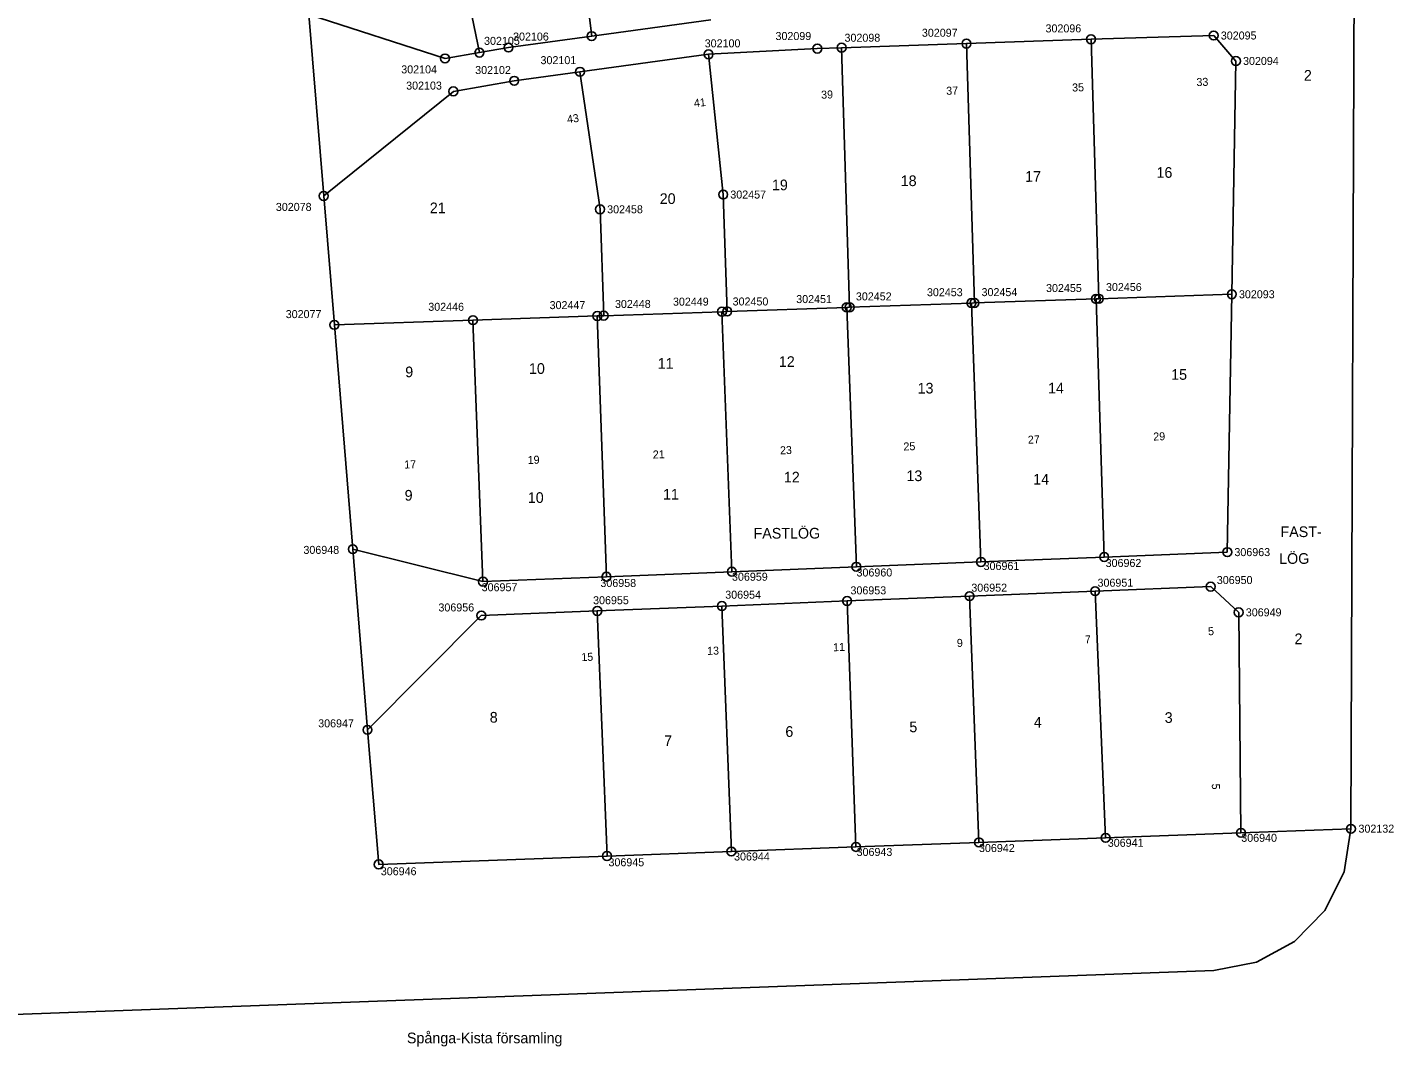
# Model space of a CAD drawing. Extents: x 141995 to 152570, y 6580184 to 6586000.
# Drawn here: x 142727.8 to 142881.4, y 6585375.4 to 6585490 of the extents above; entities that cross this region are included whole.
import ezdxf

# ---------------------------------------------------------------- set-up
doc = ezdxf.new("R2010")
doc.units = 0
for name, color, linetype in [('Level 10', 7, 'Continuous'), ('Level 13', 7, 'Continuous'), ('Level 5', 7, 'Continuous'), ('Level 51', 7, 'Continuous'), ('Level 53', 7, 'Continuous'), ('Level 54', 7, 'Continuous'), ('Level 55', 7, 'Continuous'), ('Level 57', 7, 'Continuous'), ('Level 58', 7, 'Continuous'), ('Level 59', 7, 'Continuous'), ('Level 6', 7, 'Continuous'), ('Level 7', 7, 'Continuous')]:
    doc.layers.add(name, color=color, linetype=linetype)

msp = doc.modelspace()

# ---------------------------------------------------------------- linework, layer by layer
at = {"layer": 'Level 10'}
for centre in [(142791.21, 6585489), (142833.35, 6585488.16), (142847.36, 6585488.65), (142861.15, 6585489.07), (142774.72, 6585486.49), (142778.59, 6585487.15), (142781.86, 6585487.72), (142804.35, 6585486.96), (142816.58, 6585487.6), (142819.31, 6585487.7), (142789.89, 6585484.99), (142863.65, 6585486.2), (142782.5, 6585483.98), (142775.66, 6585482.79), (142806, 6585471.19), (142761.08, 6585471.03), (142792.15, 6585469.53), (142833.91, 6585458.99), (142834.25, 6585459), (142847.92, 6585459.46), (142848.24, 6585459.47), (142863.19, 6585459.98), (142791.84, 6585457.54), (142792.56, 6585457.57), (142805.86, 6585458.02), (142806.45, 6585458.05), (142819.89, 6585458.51), (142820.21, 6585458.52), (142762.28, 6585456.54), (142777.86, 6585457.07), (142764.35, 6585431.32), (142834.98, 6585429.89), (142848.84, 6585430.44), (142862.68, 6585430.99), (142792.87, 6585428.22), (142806.97, 6585428.79), (142820.97, 6585429.34), (142778.99, 6585427.67), (142847.82, 6585426.6), (142860.81, 6585427.11), (142819.93, 6585425.5), (142833.7, 6585426.04), (142778.8, 6585423.86), (142791.84, 6585424.38), (142805.85, 6585424.93), (142863.96, 6585424.22), (142766, 6585411.01), (142864.22, 6585399.43), (142876.58, 6585399.88), (142820.93, 6585397.85), (142834.76, 6585398.35), (142849, 6585398.87), (142767.26, 6585395.88), (142792.94, 6585396.82), (142806.92, 6585397.33)]:
    msp.add_circle(centre, 0.5, dxfattribs=at)
at = {"layer": 'Level 13'}
for points in [[(142876.58, 6585399.88), (142875.82, 6585395.06)], [(142875.82, 6585395.06), (142873.64, 6585390.7)], [(142873.64, 6585390.7), (142870.24, 6585387.2)], [(142865.96, 6585384.89), (142870.24, 6585387.2)], [(142865.96, 6585384.89), (142861.17, 6585383.96)], [(142861.17, 6585383.96), (142627.09, 6585375.39)]]:
    msp.add_lwpolyline(points, dxfattribs=at)
at = {"layer": 'Level 5'}
for points in [[(142877, 6585504.71), (142876.58, 6585399.88)], [(142761.08, 6585471.03), (142759.4, 6585491.42)], [(142762.28, 6585456.54), (142761.08, 6585471.03)], [(142762.28, 6585456.54), (142764.35, 6585431.32)], [(142766, 6585411.01), (142764.35, 6585431.32)], [(142767.26, 6585395.88), (142766, 6585411.01)], [(142864.22, 6585399.43), (142849, 6585398.87)], [(142864.22, 6585399.43), (142876.58, 6585399.88)], [(142834.76, 6585398.35), (142820.93, 6585397.85)], [(142849, 6585398.87), (142834.76, 6585398.35)], [(142792.94, 6585396.82), (142767.26, 6585395.88)], [(142806.92, 6585397.33), (142792.94, 6585396.82)], [(142820.93, 6585397.85), (142806.92, 6585397.33)]]:
    msp.add_lwpolyline(points, dxfattribs=at)
at = {"layer": 'Level 6'}
msp.add_lwpolyline([(142705.65, 6585551.64), (142759.4, 6585491.42), (142761.08, 6585471.03), (142762.28, 6585456.54), (142764.35, 6585431.32), (142766, 6585411.01), (142767.26, 6585395.88), (142792.94, 6585396.82), (142806.92, 6585397.33), (142820.93, 6585397.85), (142834.76, 6585398.35), (142849, 6585398.87), (142864.22, 6585399.43), (142876.58, 6585399.88), (142877, 6585504.71), (142876.45, 6585516.74), (142874.71, 6585528.64), (142871.79, 6585540.33), (142867.72, 6585551.66), (142862.55, 6585562.53), (142856.33, 6585572.84), (142849.11, 6585582.47), (142840.97, 6585591.35), (142792.82, 6585638.84)], dxfattribs=at)
at = {"layer": 'Level 7'}
for points in [[(142787.53, 6585518.53), (142791.21, 6585489)], [(142772.54, 6585516.47), (142778.59, 6585487.15)], [(142759.4, 6585491.42), (142774.72, 6585486.49)], [(142791.21, 6585489), (142804.6, 6585490.83)], [(142781.86, 6585487.72), (142791.21, 6585489)], [(142847.36, 6585488.65), (142833.35, 6585488.16)], [(142861.15, 6585489.07), (142847.36, 6585488.65)], [(142848.24, 6585459.47), (142847.36, 6585488.65)], [(142863.65, 6585486.2), (142861.15, 6585489.07)], [(142774.72, 6585486.49), (142778.59, 6585487.15)], [(142778.59, 6585487.15), (142781.86, 6585487.72)], [(142816.58, 6585487.6), (142804.35, 6585486.96)], [(142819.31, 6585487.7), (142816.58, 6585487.6)], [(142833.35, 6585488.16), (142819.31, 6585487.7)], [(142820.21, 6585458.52), (142819.31, 6585487.7)], [(142834.25, 6585459), (142833.35, 6585488.16)], [(142804.35, 6585486.96), (142789.89, 6585484.99)], [(142806, 6585471.19), (142804.35, 6585486.96)], [(142863.19, 6585459.98), (142863.65, 6585486.2)], [(142782.5, 6585483.98), (142775.66, 6585482.79)], [(142789.89, 6585484.99), (142782.5, 6585483.98)], [(142792.15, 6585469.53), (142789.89, 6585484.99)], [(142775.66, 6585482.79), (142761.08, 6585471.03)], [(142806.45, 6585458.05), (142806, 6585471.19)], [(142792.56, 6585457.57), (142792.15, 6585469.53)], [(142834.25, 6585459), (142847.92, 6585459.46)], [(142847.92, 6585459.46), (142848.24, 6585459.47)], [(142847.92, 6585459.46), (142848.84, 6585430.44)], [(142848.24, 6585459.47), (142863.19, 6585459.98)], [(142863.19, 6585459.98), (142862.68, 6585430.99)], [(142792.56, 6585457.57), (142805.86, 6585458.02)], [(142805.86, 6585458.02), (142806.45, 6585458.05)], [(142805.86, 6585458.02), (142806.97, 6585428.79)], [(142806.45, 6585458.05), (142819.89, 6585458.51)], [(142819.89, 6585458.51), (142820.21, 6585458.52)], [(142819.89, 6585458.51), (142820.97, 6585429.34)], [(142820.21, 6585458.52), (142833.91, 6585458.99)], [(142833.91, 6585458.99), (142834.25, 6585459)], [(142833.91, 6585458.99), (142834.98, 6585429.89)], [(142762.28, 6585456.54), (142777.86, 6585457.07)], [(142777.86, 6585457.07), (142791.84, 6585457.54)], [(142777.86, 6585457.07), (142778.99, 6585427.67)], [(142791.84, 6585457.54), (142792.56, 6585457.57)], [(142791.84, 6585457.54), (142792.87, 6585428.22)], [(142764.35, 6585431.32), (142778.99, 6585427.67)], [(142834.98, 6585429.89), (142848.84, 6585430.44)], [(142848.84, 6585430.44), (142862.68, 6585430.99)], [(142792.87, 6585428.22), (142806.97, 6585428.79)], [(142806.97, 6585428.79), (142820.97, 6585429.34)], [(142820.97, 6585429.34), (142834.98, 6585429.89)], [(142778.99, 6585427.67), (142792.87, 6585428.22)], [(142860.81, 6585427.11), (142847.82, 6585426.6)], [(142863.96, 6585424.22), (142860.81, 6585427.11)], [(142833.7, 6585426.04), (142819.93, 6585425.5)], [(142847.82, 6585426.6), (142833.7, 6585426.04)], [(142834.76, 6585398.35), (142833.7, 6585426.04)], [(142849, 6585398.87), (142847.82, 6585426.6)], [(142791.84, 6585424.38), (142778.8, 6585423.86)], [(142805.85, 6585424.93), (142791.84, 6585424.38)], [(142792.94, 6585396.82), (142791.84, 6585424.38)], [(142819.93, 6585425.5), (142805.85, 6585424.93)], [(142806.92, 6585397.33), (142805.85, 6585424.93)], [(142820.93, 6585397.85), (142819.93, 6585425.5)], [(142864.22, 6585399.43), (142863.96, 6585424.22)], [(142778.8, 6585423.86), (142766, 6585411.01)]]:
    msp.add_lwpolyline(points, dxfattribs=at)

# ---------------------------------------------------------------- texts
at = {"layer": 'Level 51'}
for s, p in [('18', (142825.96, 6585472.14)), ('17', (142839.95, 6585472.62)), ('16', (142854.72, 6585473.07)), ('19', (142811.48, 6585471.67)), ('21', (142773.01, 6585469.09)), ('20', (142798.86, 6585470.13)), ('15', (142856.37, 6585450.36)), ('12', (142812.82, 6585438.82)), ('13', (142826.6, 6585438.97)), ('14', (142840.86, 6585438.59)), ('9', (142770.18, 6585436.78)), ('11', (142799.23, 6585436.89)), ('10', (142784.03, 6585436.52)), ('8', (142779.75, 6585411.82)), ('5', (142826.93, 6585410.74)), ('4', (142840.93, 6585411.27)), ('3', (142855.64, 6585411.79)), ('7', (142799.36, 6585409.19)), ('6', (142812.99, 6585410.22))]:
    msp.add_text(s, height=1.2, rotation=0.049, dxfattribs=at).set_placement(p)
at = {"layer": 'Level 53'}
for s, rotation, p in [('302096', 0.049, (142842.24, 6585489.42)), ('302105', 0.049, (142779.11, 6585488.02)), ('302106', 0.049, (142782.37, 6585488.5)), ('302100', 0.049, (142803.92, 6585487.74)), ('302099', 0.049, (142811.88, 6585488.56)), ('302098', 0.049, (142819.64, 6585488.37)), ('302097', 0.049, (142828.34, 6585488.93)), ('302095', 0.049, (142861.95, 6585488.62)), ('302104', 0.049, (142769.8, 6585484.81)), ('302102', 0.049, (142778.11, 6585484.74)), ('302101', 0.049, (142785.46, 6585485.85)), ('302094', 0.049, (142864.45, 6585485.76)), ('302103', 0.049, (142770.35, 6585482.99)), ('302457', 0.049, (142806.8, 6585470.74)), ('302078', 0.049, (142755.7, 6585469.35)), ('302458', 0.049, (142792.95, 6585469.08)), ('302455', 0.049, (142842.3, 6585460.23)), ('302456', 0.049, (142849.04, 6585460.34)), ('302448', 0.049, (142793.83, 6585458.44)), ('302449', 0.049, (142800.35, 6585458.7)), ('302450', 0.049, (142807.06, 6585458.72)), ('302451', 0.049, (142814.21, 6585458.99)), ('302452', 0.049, (142820.92, 6585459.29)), ('302453', 0.049, (142828.91, 6585459.76)), ('302454', 0.049, (142835.05, 6585459.77)), ('302093', 0.049, (142863.99, 6585459.53)), ('302077', 0.049, (142756.81, 6585457.3)), ('302446', 0.049, (142772.84, 6585458.12)), ('302447', 0.049, (142786.48, 6585458.31)), ('306948', 0.049, (142758.8, 6585430.79)), ('306962', 0.049, (142849, 6585429.32)), ('306963', 0.049, (142863.48, 6585430.54)), ('306959', 0.049, (142806.99, 6585427.77)), ('306960', 0.049, (142820.99, 6585428.25)), ('306961', 0.049, (142835.28, 6585428.98)), ('306957', 0.049, (142778.84, 6585426.59)), ('306958', 0.049, (142792.19, 6585427.07)), ('306953', 0.049, (142820.31, 6585426.24)), ('306952', 0.049, (142833.9, 6585426.54)), ('306951', 0.049, (142848.09, 6585427.1)), ('306950', 0.049, (142861.5, 6585427.4)), ('306955', 0.049, (142791.37, 6585425.13)), ('306954', 0.049, (142806.23, 6585425.75)), ('306956', 0.049, (142773.98, 6585424.32)), ('306949', 0.049, (142864.76, 6585423.77)), ('306947', 0.049, (142760.46, 6585411.29)), ('302132', 0.0493, (142877.43, 6585399.45)), ('306942', 0.0493, (142834.76, 6585397.27)), ('306941', 0.0493, (142849.24, 6585397.86)), ('306940', 0.0493, (142864.25, 6585398.42)), ('306945', 0.049, (142793.1, 6585395.67)), ('306944', 0.049, (142807.22, 6585396.32)), ('306943', 0.0493, (142821, 6585396.83)), ('306946', 0.049, (142767.5, 6585394.66))]:
    msp.add_text(s, height=0.9, rotation=rotation, dxfattribs=at).set_placement(p)
at = {"layer": 'Level 54'}
for s, rotation, p in [('33', 1.8381, (142859.22, 6585483.38)), ('39', 1.9661, (142817.02, 6585481.96)), ('37', 1.9241, (142831.09, 6585482.4)), ('35', 1.6861, (142845.24, 6585482.77)), ('41', 6.0513, (142802.75, 6585481.01)), ('43', 8.3044, (142788.5, 6585479.19)), ('27', 2.1511, (142840.27, 6585443.17)), ('29', 1.9771, (142854.37, 6585443.53)), ('21', 1.9531, (142798.1, 6585441.51)), ('23', 2.1711, (142812.4, 6585441.98)), ('25', 2.0871, (142826.28, 6585442.41)), ('17', 2.2141, (142770.15, 6585440.38)), ('19', 2.1341, (142784.03, 6585440.89)), ('5', 3.9112, (142860.54, 6585421.63)), ('9', 2.2051, (142832.29, 6585420.32)), ('7', 2.2811, (142846.68, 6585420.71)), ('15', 2.2951, (142790.06, 6585418.73)), ('13', 2.0971, (142804.2, 6585419.43)), ('11', 2.2051, (142818.37, 6585419.84))]:
    msp.add_text(s, height=0.9, rotation=rotation, dxfattribs=at).set_placement(p)
at = {"layer": 'Level 55'}
msp.add_text('5', height=0.9, rotation=270.327, dxfattribs=at).set_placement((142860.94, 6585404.96))
at = {"layer": 'Level 57'}
msp.add_text('Spånga-Kista församling', height=1.2, dxfattribs=at).set_placement((142770.44, 6585375.77))
at = {"layer": 'Level 58'}
for s, p in [('FASTLÖG', (142809.41, 6585432.51)), ('FAST-', (142868.66, 6585432.68)), ('LÖG', (142868.51, 6585429.67))]:
    msp.add_text(s, height=1.2, rotation=0.049, dxfattribs=at).set_placement(p)
at = {"layer": 'Level 59'}
for s, p in [('2', (142871.29, 6585483.99)), ('9', (142770.25, 6585450.65)), ('10', (142784.16, 6585451.03)), ('11', (142798.63, 6585451.61)), ('12', (142812.26, 6585451.81)), ('13', (142827.86, 6585448.82)), ('14', (142842.52, 6585448.83)), ('2', (142870.24, 6585420.64))]:
    msp.add_text(s, height=1.2, rotation=0.049, dxfattribs=at).set_placement(p)

doc.saveas('drawing.dxf')
